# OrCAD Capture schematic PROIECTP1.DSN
size A
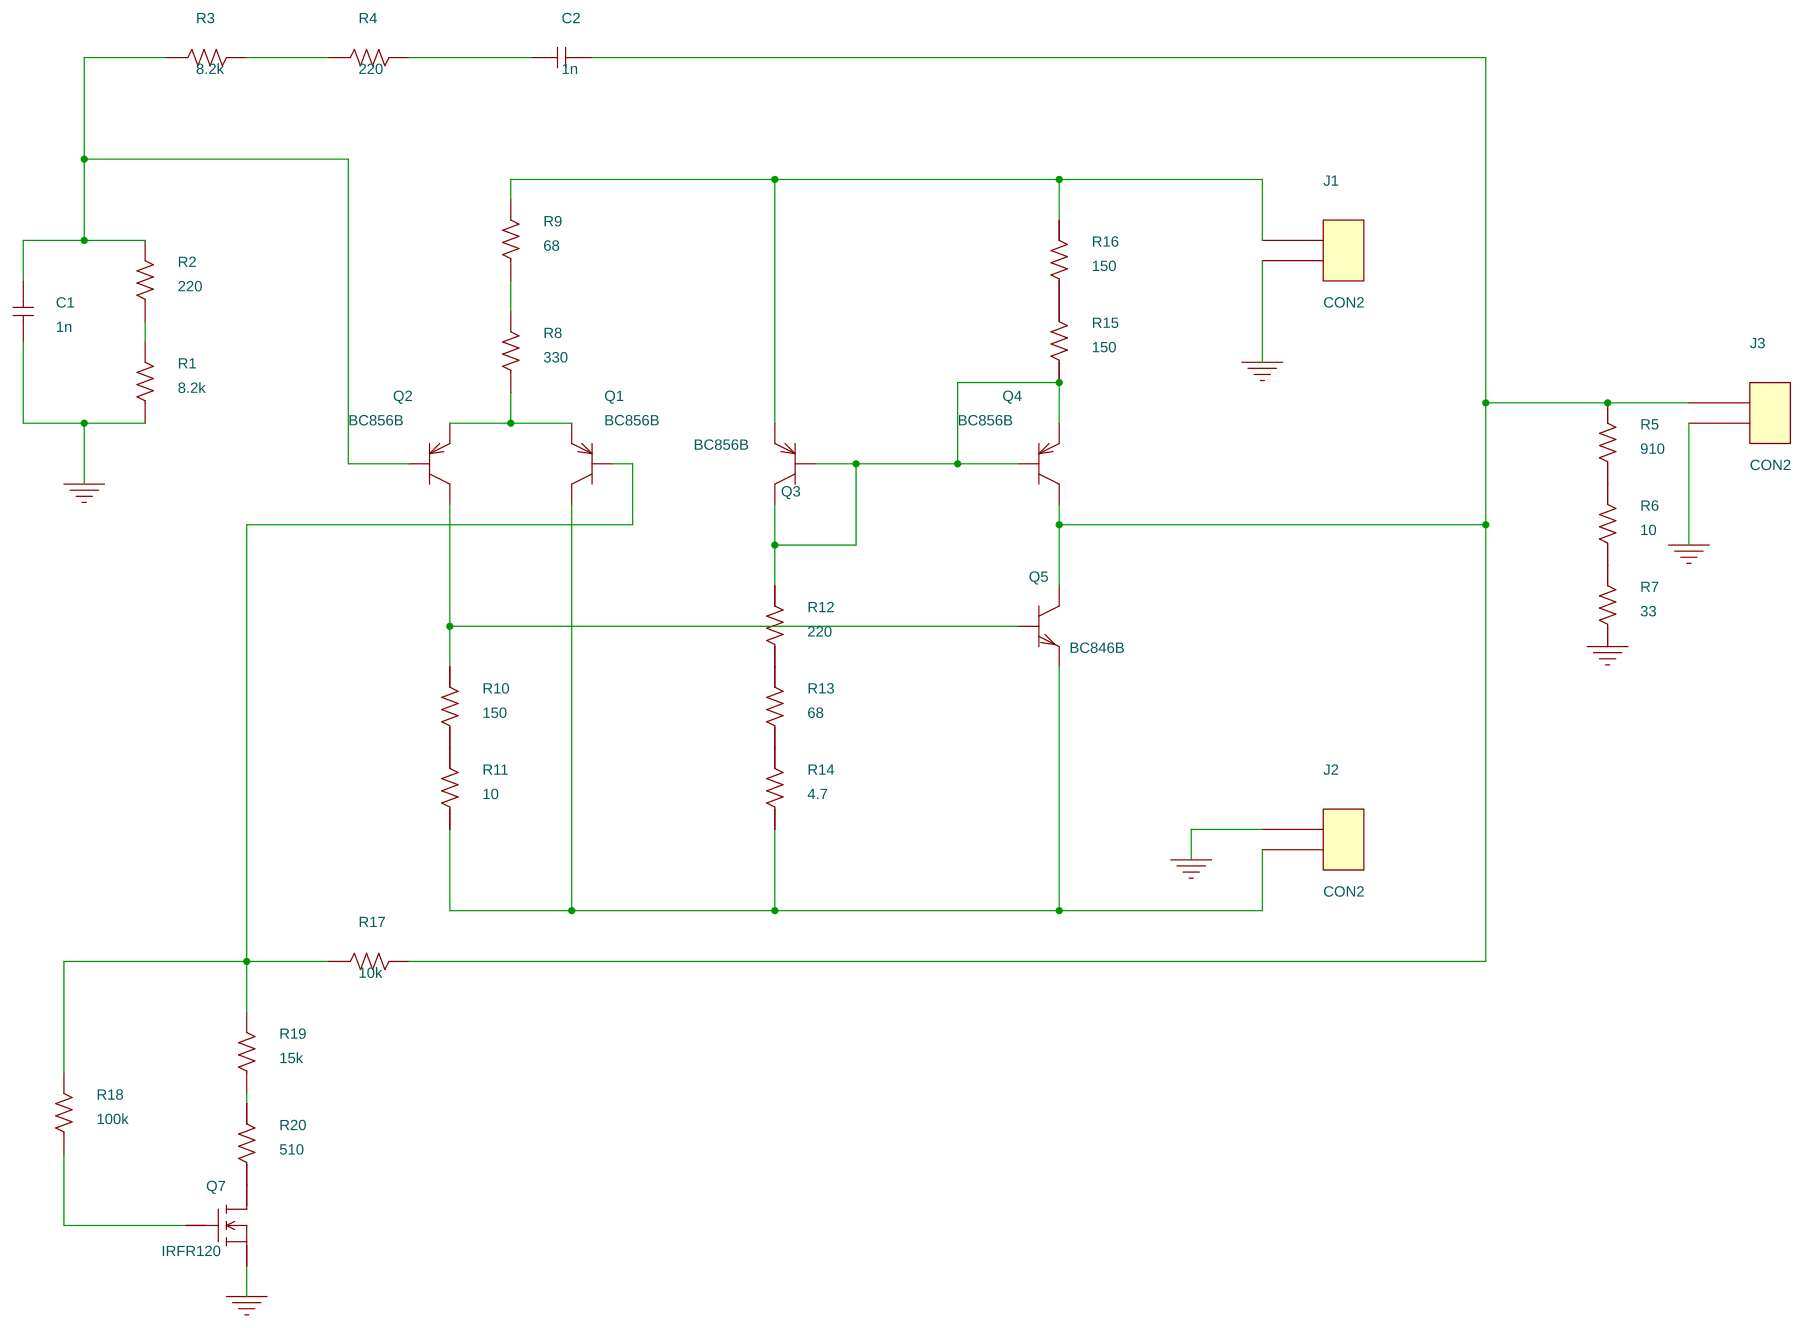
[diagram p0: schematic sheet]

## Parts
C1  1n  [SMC0805]
C2  1n  [SMC0805]
J1  CON2  [SMR2512]
J2  CON2  [SMR2512]
J3  CON2  [SMR2512]
Q1  BC856B  [SOT23]
Q2  BC856B  [SOT23]
Q3  BC856B  [SOT23]
Q4  BC856B  [SOT23]
Q5  BC846B  [SOT23]
Q7  IRFR120  [to252aa]
R1  8.2k  [SMR0805]
R2  220  [SMR0805]
R3  8.2k  [SMR0805]
R4  220  [SMR0805]
R5  910  [SMR0805]
R6  10  [SMR0805]
R7  33  [SMR0805]
R8  330  [SMR0805]
R9  68  [SMR0805]
R10  150  [SMR0805]
R11  10  [SMR0805]
R12  220  [SMR0805]
R13  68  [SMR0805]
R14  4.7  [SMR0805]
R15  150  [SMR0805]
R16  150  [SMR0805]
R17  10k  [SMR0805]
R18  100k  [SMR0805]
R19  15k  [SMR0805]
R20  510  [SMR0805]

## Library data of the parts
C1 C2 = C
J1-J3 = CON2
Q1-Q4 = BC856B
Q5 = BC846B
Q7 = IRFR120
R1-R20 = R

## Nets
GND: C1.1 J1.2 J2.1 J3.2 Q7.3(S) R1.1 R7.1
N07562: R1.2 R2.1
N07566: C1.2 Q2.1(b) R2.2 R3.1
N07674: R3.2 R4.1
N07678: C2.1 R4.2
N07682: C2.2 J3.1 Q4.3(c) Q5.3(c) R5.2 R17.2
N07786: Q1.2(e) Q2.2(e) R8.1
N07830: J1.1 Q3.2(e) R9.2 R16.2
N07834: Q2.3(c) Q5.1(b) R10.2
N07854: J2.2 Q1.3(c) Q5.2(e) R11.1 R14.1
N07900: Q3.1(b) Q3.3(c) Q4.1(b) Q4.2(e) R12.2 R15.1
N08156: Q1.1(b) R17.1 R18.2 R19.2
N08192: Q7.1(G) R18.1
N08330: R8.2 R9.1
N08354: R19.1 R20.2
N08573: R13.1 R14.2
N08575: R6.1 R7.2
N08576: R10.1 R11.2
N08577: R5.1 R6.2
N08578: R15.2 R16.1
N08579: R12.1 R13.2
N08718: Q7.2(D) R20.1
